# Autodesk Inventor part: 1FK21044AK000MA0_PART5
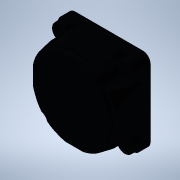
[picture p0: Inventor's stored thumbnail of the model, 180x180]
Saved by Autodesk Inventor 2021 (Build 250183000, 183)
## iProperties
Created: 2025-04
Part Number: 1FK21044AK000MA0_PART5
Material: Generic
Catalog Web Link: www.3dfindit.com
Description: -Servo synchronous motor
Document SubType Name: Modeling
Designer: psAdmin
Mass: 3.92604 g
Surface Area: 17.9521 cm^2
Volume: 3.92604 cm^3
Density: 1 g/cm^3
Appearance: PSOLRGB-48-56-69
Category: PARTsolutions
Title: 1FK21044AK000MA0_PART5
Author: Cadenas PARTsolutions
Comments: Servo synchronous motor
Sending System: PARTsolutions
Preprocessor: ST-DEVELOPER v19.3
PSOL_IDENT_0: {$CADENAS_DATA/23d-libs/siemens_ag/_cat_/87/f4/1fk21044ak000ma0.prj},213 {VTYP=3D},{NB=1FK21044AK000
PSOL_IDENT_1: MA0_PART5},{LINA=1FK21044AK000MA0_PART5},{NN=1FK21044AK000MA0_PART5},{NOPRJ=TRUE},{DATE=19.08.2025 1
PSOL_IDENT_2: 4:00:48},{GEOMDATE=30.07.2025 02:00:50},{VERSION=},{LINEID=10},{WBVAR=},{WBNUMERIC=}  {NB=1FK21044AK
PSOL_IDENT_3: 000MA0_PART5},{LINA=1FK21044AK000MA0_PART5},{KT=DUMMY},{PREVIEW=../../../_pool_/cb/72/p_d211_xx_0043
PSOL_IDENT_4: 4j.png},{DESCSHORT=SIMOTICS S-1FK2 HD, SINAMICS S210 3AC 400V-480V, 0.95 Nm, 6000 rpm},{DESCLONG=SIM
PSOL_IDENT_5: OTICS S-1FK2 HD servo motor M0=1.27 Nm; PN = 0.6 kW at nN=6000 rpm (380-480 V); PN = 0.4 kW at nN=30
PSOL_IDENT_6: 00 rpm (200-240 V); degree of protection IP64; cylindrical shaft D19x40mm; absolute encoder 22-bit +
PSOL_IDENT_7: 12-bit multiturn (encoder AM22DQC); with OCC interface; plug size M17, rotatable; SIMOTICS S-1FK2 s
PSOL_IDENT_8: ervomotorfor a wide range of uses in industrial environments. SIMOTICS S‑1FK2 servomotors are compac
PSOL_IDENT_9: t synchronous motors with a high dynamic performance that set themselves apart as a result of their
PSOL_IDENT_10: high power density, degree of protection and overload capability. The motors are available in two va
PSOL_IDENT_11: riants: as High Dynamic variant (highest dynamic performance as a result of the low intrinsic moment
PSOL_IDENT_12: of inertia for applications demanding a high dynamic performance with low moved masses) - and as Co
PSOL_IDENT_13: mpact variant (precise and stable closed-loop control for medium up to large moved masses as a resul
PSOL_IDENT_14: t of a medium intrinsic moment of inertia). SIMOTICSS‑1FK2 servomotors fully exploit their strengths
PSOL_IDENT_15: in a system with the SINAMICSS210 frequency converter and simple connection using the one cable con
PSOL_IDENT_16: nection (OCC). Advantages include the short control and positioning times, fast and precise correcti
PSOL_IDENT_17: on of disturbing quantities as well as stable control with a high dynamic performance. The servo mot
PSOL_IDENT_18: ors can be configured to address a wide range of requirements. For example with and without holding
PSOL_IDENT_19: brake, IP64 or IP65 degree of protection, singleturn or multiturn absolute encoders - to name just a
PSOL_IDENT_20: few. Further, the servomotors are available in different shaft heights extending from 20 to 100. A
PSOL_IDENT_21: shaft sealing ring is available to achieve an IP65 degree of protection and for subsequent mounting
PSOL_IDENT_22: at the motor or as spare part. SIMOTICS - the optimum motor for each and every motion control applic
PSOL_IDENT_23: ation.},{INTNO=195125056312},{SUPPLIERALTNO=1FK2104-4AK00-0MA0},{MANUID=1FK21044AK000MA0},{MANUNAME=
PSOL_IDENT_24: Siemens},{MANUTYPEDESC=Synchronous motor 1FK2-HD 1,27 Nm},{AAU732=SIMOTICS},{AAO057=S-1FK2},{AAU734=
PSOL_IDENT_25: SIMOTICS S-1FK2 HD servo motor M0=1.27 Nm; PN = 0.6 kW at nN=6000 rpm (380-480 V); PN = 0.4 kW at nN=
PSOL_IDENT_26: 3000 rpm (200-240 V); degree of protection IP64; cylindrical shaft D19x40mm; absolute encoder 22-bit
PSOL_IDENT_27: + 12-bit multiturn (encoder AM22DQC); with OCC interface; plug size M17, rotatable;},{AAW338=Synchr
PSOL_IDENT_28: onous motor 1FK2-HD 1,27 Nm},{AAO742=SIMOTICS},{AAO663=4042948690994},{NOCUPEROU=1},{PRICEQUANTITY=1
PSOL_IDENT_29: },{QUANTITYMIN=1},{QUANTITYINT=1},{CTN=85015100},{COO=DE},{AAO676=1FK2104-4AK00-0MA0},{AAO677=Siemen
PSOL_IDENT_30: s AG},{ORDERUNIT=C62},{CONTENTUNIT=C62}
NB: 1FK21044AK000MA0_PART5
NT: Servo synchronous motor
NBSYN: $MANUID._PART5
LINA: 1FK21044AK000MA0_PART5
CATALOG: SIEMENS
PREVIEW: ../../../_pool_/cb/72/p_d211_xx_00434j.png
DESCSHORT: SIMOTICS S-1FK2 HD, SINAMICS S210 3AC 400V-480V, 0.95 Nm, 6000 rpm
DESCLONG: SIMOTICS S-1FK2 HD servo motor M0=1.27 Nm; PN = 0.6 kW at nN=6000 rpm (380-480 V); PN = 0.4 kW at nN=3000 rpm (200-240 V); degree of protection IP64; cylindrica
INTNO: 195125056312
SUPPLIERALTNO: 1FK2104-4AK00-0MA0
MANUID: 1FK21044AK000MA0
MANUNAME: Siemens
MANUTYPEDESC: Synchronous motor 1FK2-HD 1,27 Nm
AAU732: SIMOTICS
AAO057: S-1FK2
AAU734: SIMOTICS S-1FK2 HD servo motor M0=1.27 Nm; PN = 0.6 kW at nN=6000 rpm (380-480 V); PN = 0.4 kW at nN=3000 rpm (200-240 V); degree of protection IP64; cylindrica
AAW338: Synchronous motor 1FK2-HD 1,27 Nm
AAO742: SIMOTICS
AAO663: 4042948690994.0
NOCUPEROU: 1
PRICEQUANTITY: 1
QUANTITYMIN: 1
QUANTITYINT: 1
CTN: 85015100
COO: DE
ARTICLENO: 1FK21044AK000MA0_PART5
BOMINFO: 1FK21044AK000MA0_PART5
CREATOR: CADENAS GmbH
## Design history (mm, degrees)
feature "2025_04_17_15_37_40_0525"
body "Solid1"
